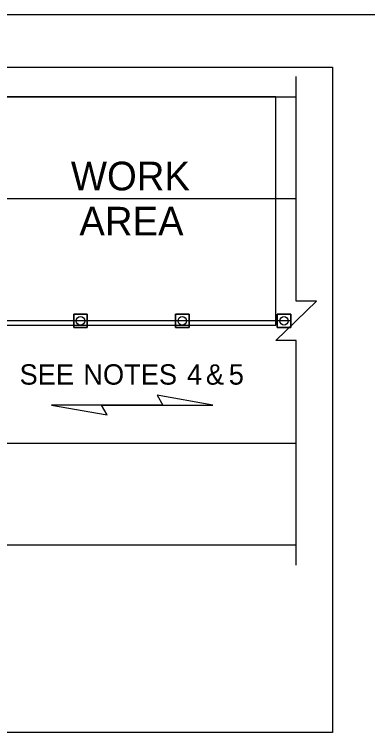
# Model space of a CAD drawing. Extents: x 99999.1 to 100095.7, y 99995 to 100010.7.
# Drawn here: x 100008.131 to 100009.243, y 100003.475 to 100005.732 of the extents above; entities that cross this region are included whole.
import ezdxf

# ---------------------------------------------------------------- set-up
doc = ezdxf.new("R2010")
doc.units = 0
for name, color, linetype in [('RD_ED_ShoulderPavedEdge', 7, 'Continuous'), ('RD_MK_LineEdgeWhite', 7, 'Continuous'), ('RD_MK_LineSkipCenter', 7, 'Continuous'), ('SH_TI_Tables', 7, 'Continuous'), ('TR_WZ_TrafficCone', 7, 'Continuous'), ('TR_WZ_WorkZoneDetails', 7, 'Continuous'), ('TR_WZ_WorkZoneTextCurrent', 7, 'Continuous')]:
    doc.layers.add(name, color=color, linetype=linetype)

msp = doc.modelspace()

# ---------------------------------------------------------------- linework, layer by layer
at = {"layer": 'RD_ED_ShoulderPavedEdge'}
for p, q in [((100000.1076, 100005.7323), (100015.6424, 100005.7323)), ((100005.1009, 100005.4735), (100009.0183, 100005.4735)), ((100005.1009, 100004.0655), (100009.0183, 100004.0655))]:
    msp.add_line(p, q, dxfattribs=at)
at = {"layer": 'RD_MK_LineEdgeWhite'}
for p, q in [((100005.1009, 100005.1535), (100009.0183, 100005.1535)), ((100005.1009, 100004.3855), (100009.0183, 100004.3855))]:
    msp.add_line(p, q, dxfattribs=at)
at = {"layer": 'RD_MK_LineSkipCenter'}
msp.add_lwpolyline([(100009.0017, 100004.7695), (100005.0844, 100004.7695)], dxfattribs=at)
at = {"layer": 'SH_TI_Tables'}
msp.add_lwpolyline([(100004.9869, 100005.5662), (100009.1323, 100005.5662), (100009.1323, 100003.4755), (100004.9869, 100003.4755)], close=True, dxfattribs=at)
at = {"layer": 'TR_WZ_TrafficCone'}
for points in [[(100008.3183, 100004.7908), (100008.3609, 100004.7908), (100008.3609, 100004.7482), (100008.3183, 100004.7482), (100008.3183, 100004.7908)], [(100008.3183, 100004.7482), (100008.3609, 100004.7482), (100008.3609, 100004.7908), (100008.3183, 100004.7908), (100008.3183, 100004.7482)], [(100008.6383, 100004.7908), (100008.6809, 100004.7908), (100008.6809, 100004.7482), (100008.6383, 100004.7482), (100008.6383, 100004.7908)], [(100008.6383, 100004.7482), (100008.6809, 100004.7482), (100008.6809, 100004.7908), (100008.6383, 100004.7908), (100008.6383, 100004.7482)], [(100008.9583, 100004.7908), (100009.0009, 100004.7908), (100009.0009, 100004.7482), (100008.9583, 100004.7482), (100008.9583, 100004.7908)], [(100008.9583, 100004.7482), (100009.0009, 100004.7482), (100009.0009, 100004.7908), (100008.9583, 100004.7908), (100008.9583, 100004.7482)]]:
    msp.add_lwpolyline(points, dxfattribs=at)
for centre in [(100008.3396, 100004.7695), (100008.6596, 100004.7695), (100008.9796, 100004.7695)]:
    msp.add_circle(centre, 0.0133, dxfattribs=at)
at = {"layer": 'TR_WZ_WorkZoneDetails'}
for p, q in [((100008.406, 100004.5049), (100008.5989, 100004.5049)), ((100008.5989, 100004.5049), (100008.406, 100004.5049))]:
    msp.add_line(p, q, dxfattribs=at)
msp.add_lwpolyline([(100009.0183, 100004.0015), (100009.0183, 100004.7075), (100008.9542, 100004.7075), (100009.0823, 100004.8314), (100009.0183, 100004.8314), (100009.0183, 100005.5375)], dxfattribs=at)
for points in [[(100008.0383, 100005.4735), (100008.0383, 100004.7562), (100008.9542, 100004.7562), (100008.9542, 100005.4735)], [(100008.7561, 100004.5049), (100008.581, 100004.5358), (100008.5989, 100004.5049)], [(100008.2488, 100004.5049), (100008.4238, 100004.4741), (100008.406, 100004.5049)]]:
    msp.add_lwpolyline(points, close=True, dxfattribs=at)

# ---------------------------------------------------------------- texts
for s, p in [('WORK', (100008.3093, 100005.1794)), ('AREA', (100008.336, 100005.0376))]:
    msp.add_text(s, height=0.09, dxfattribs=at).set_placement(p)
at = {"layer": 'TR_WZ_WorkZoneTextCurrent'}
for s, p in [('SEE', (100008.1479, 100004.5689)), ('NOTES', (100008.3484, 100004.5689)), ('4', (100008.6744, 100004.5689)), ('&', (100008.7339, 100004.5689)), ('5', (100008.8058, 100004.5689))]:
    msp.add_text(s, height=0.064, dxfattribs=at).set_placement(p)

doc.saveas('drawing.dxf')
